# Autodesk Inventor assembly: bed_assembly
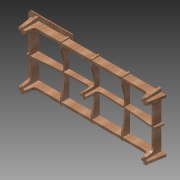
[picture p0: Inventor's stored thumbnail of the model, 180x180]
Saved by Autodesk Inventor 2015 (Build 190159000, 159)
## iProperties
Created: 2015-04
Part Number: bed_assembly
Document SubType Name: Assembly
Designer: sungeun
Author: sungeun
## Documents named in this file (8)
- \\psf\Home\Desktop\bed_assembly.iam
- \\psf\Home\Desktop\leg1.ipt
- \\psf\Home\Desktop\leg2.ipt
- \\psf\Home\Desktop\bridge2.ipt
- \\psf\Home\Desktop\bridge1.ipt
- \\psf\Home\Desktop\leg3.ipt
- \\psf\Home\Desktop\cover1.ipt
- \\psf\Home\Desktop\cover2.ipt
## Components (10 placed, 7 different names)
1. leg2:1 — Mate:14, Flush:7, Flush:11, Mate:20, Mate:21, Mate:22, Mate:23, Flush:12, Mate:31
2. leg2:2 — Mate:16, Mate:19, Flush:9, Mate:27
3. bridge2:1 — Mate:33, Flush:16, Mate:34
4. bridge2:2 — Flush:15, Mate:29, Mate:30
5. bridge1:1 — Mate:14, Flush:7, Mate:16, Flush:10, Mate:30, Mate:31, Mate:32, Mate:33
6. leg3:1 — Mate:28, Flush:14, Mate:32
7. cover1:1 — Mate:19, Flush:9, Flush:10, Mate:25, Mate:26, Flush:13
8. leg1:1 — Flush:11, Mate:20, Mate:21
9. leg1:2 — Mate:22, Mate:23, Flush:12, Mate:24, Mate:25, Mate:27, Mate:28, Flush:14, Flush:15, Mate:29, Flush:16, Mate:34
10. cover2:1 — Mate:24, Mate:26, Flush:13
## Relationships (27: Mate 18, Flush 9)
- Mate:14: leg2:1 ↔ bridge1:1
- Flush:7: leg2:1 ↔ bridge1:1
- Mate:16: leg2:2 ↔ bridge1:1
- Mate:19: leg2:2 ↔ cover1:1
- Flush:9: leg2:2 ↔ cover1:1
- Flush:10: bridge1:1 ↔ cover1:1
- Flush:11: leg2:1 ↔ leg1:1
- Mate:20: leg2:1 ↔ leg1:1
- Mate:21: leg2:1 ↔ leg1:1
- Mate:22: leg2:1 ↔ leg1:2
- Mate:23: leg2:1 ↔ leg1:2
- Flush:12: leg2:1 ↔ leg1:2
- Mate:24: leg1:2 ↔ cover2:1
- Mate:25: cover1:1 ↔ leg1:2
- Mate:26: cover1:1 ↔ cover2:1
- Flush:13: cover1:1 ↔ cover2:1
- Mate:27: leg2:2 ↔ leg1:2
- Mate:28: leg3:1 ↔ leg1:2
- Flush:14: leg3:1 ↔ leg1:2
- Flush:15: bridge2:2 ↔ leg1:2
- Mate:29: bridge2:2 ↔ leg1:2
- Mate:30: bridge2:2 ↔ bridge1:1
- Mate:31: leg2:1 ↔ bridge1:1
- Mate:32: bridge1:1 ↔ leg3:1
- Mate:33: bridge2:1 ↔ bridge1:1
- Flush:16: bridge2:1 ↔ leg1:2
- Mate:34: bridge2:1 ↔ leg1:2
